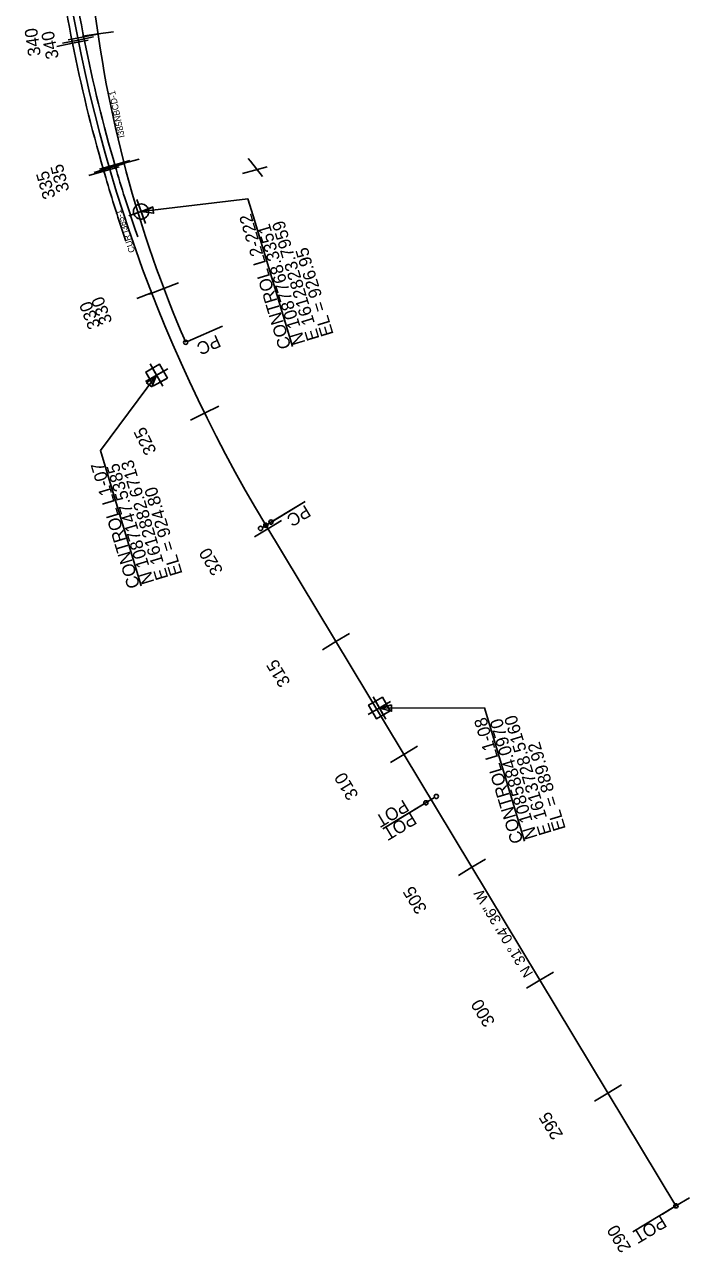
# Model space of a CAD drawing. Extents: x 1603447 to 1622636, y 1083818 to 1103958.
# Drawn here: x 1612382 to 1614905, y 1083818 to 1088478 of the extents above; entities that cross this region are included whole.
import ezdxf

# ---------------------------------------------------------------- set-up
doc = ezdxf.new("R2010")
doc.units = 0
for name, color, linetype in [('Level 1', 7, 'Continuous'), ('RD_HC_Points', 7, 'Continuous'), ('RD_HC_SUR_Bearing_TX400', 7, 'Continuous'), ('RD_HC_SUR_CL400', 7, 'Continuous'), ('RD_HC_SUR_PC_PT_400', 7, 'Continuous'), ('RD_HC_SUR_Tic400', 7, 'Continuous'), ('RD_HC_SUR_TX_Sta400', 7, 'Continuous'), ('RD_SHT_Misc1', 7, 'Continuous'), ('RD_TX_Misc1', 7, 'Continuous')]:
    doc.layers.add(name, color=color, linetype=linetype)

msp = doc.modelspace()

# ---------------------------------------------------------------- linework, layer by layer
at = {"layer": 'RD_HC_Points'}
for p, q in [((1613248.8, 1087751.3), (1613398, 1087255.6)), ((1612687.5, 1086802.4), (1612824.4, 1086347.2)), ((1614142.4, 1085834), (1614279.3, 1085379))]:
    msp.add_line(p, q, dxfattribs=at)
for points in [[(1613248.8, 1087751.3), (1613229.2, 1087816.4), (1612823.8, 1087768.3)], [(1612687.5, 1086802.4), (1612669.6, 1086861.9), (1612882.7, 1087147.5)], [(1614142.4, 1085834), (1614127.1, 1085884.6), (1613728.5, 1085884.1)]]:
    msp.add_lwpolyline(points, dxfattribs=at)
for points in [[(1612868.4, 1087786.1), (1612823.8, 1087768.3), (1612871.3, 1087761.5)], [(1612864.9, 1087102.9), (1612882.7, 1087147.5), (1612845, 1087117.8)], [(1613774.9, 1085896.6), (1613728.5, 1085884.1), (1613774.9, 1085871.7)]]:
    msp.add_lwpolyline(points, close=True, dxfattribs=at)
at = {"layer": 'RD_HC_SUR_CL400'}
for p, q in [((1612689.6, 1087897.9), (1612681.1, 1087927)), ((1612811.9, 1087671.8), (1612802, 1087700.5)), ((1614854, 1083994.9), (1613297.3, 1086577.7))]:
    msp.add_line(p, q, dxfattribs=at)
for centre, radius, start, end in [((1618204.6, 1089535.2), 5752.8, 186.3858, 196.23352), ((1618204.6, 1089535.2), 5729.6, 186.3858, 211.0768), ((1618204.6, 1089535.2), 5706.3, 186.3858, 196.2335), ((1617212.5, 1089104.4), 4600, 186.3858, 203.4744), ((1617613.8, 1089363.2), 5091, 196.2335, 199.0628), ((1617623, 1089334.3), 5138.3, 196.2335, 199.0628)]:
    msp.add_arc(centre, radius, start, end, dxfattribs=at)
at = {"layer": 'RD_HC_SUR_PC_PT_400'}
for p, q in [((1613000.5, 1087275.2), (1613132.3, 1087332.8)), ((1613284.3, 1086569.8), (1613407.4, 1086644)), ((1613304.2, 1086581.8), (1613427.3, 1086656)), ((1613324.1, 1086593.8), (1613447.2, 1086668)), ((1613937.9, 1085544.4), (1613780.8, 1085449.7)), ((1613898.1, 1085520.4), (1613741, 1085425.7)), ((1614847.1, 1083990.7), (1614690, 1083896.1))]:
    msp.add_line(p, q, dxfattribs=at)
for centre in [(1612993.2, 1087272), (1613317.2, 1086589.7), (1613277.4, 1086565.7), (1613297.3, 1086577.7), (1613904.9, 1085524.5), (1613944.7, 1085548.5), (1614854, 1083994.9)]:
    msp.add_circle(centre, 8, dxfattribs=at)
at = {"layer": 'RD_HC_SUR_Tic400'}
for p, q in [((1612584.8, 1088419.1), (1612525.9, 1088407.4)), ((1612606, 1088431.5), (1612547.1, 1088419.9)), ((1612563.5, 1088406.6), (1612622.4, 1088418.4)), ((1612584.8, 1088419.1), (1612643.6, 1088430.8)), ((1612660.4, 1088442.2), (1612601, 1088433.5)), ((1612606, 1088431.5), (1612664.9, 1088443.1)), ((1612660.4, 1088442.2), (1612719.8, 1088450.8)), ((1612563.5, 1088406.6), (1612504.7, 1088394.9)), ((1612605.1, 1088321.2), (1612605.1, 1088321.2)), ((1612626.2, 1088333.6), (1612626.2, 1088333.6)), ((1612675.8, 1088343.4), (1612675.8, 1088343.4)), ((1612584, 1088308.8), (1612584, 1088308.8)), ((1612648.1, 1088236), (1612648.1, 1088236)), ((1612693.3, 1088244.9), (1612693.3, 1088244.9)), ((1612606.2, 1088211.3), (1612606.2, 1088211.3)), ((1612627.1, 1088223.6), (1612627.1, 1088223.6)), ((1612671.7, 1088138.8), (1612671.7, 1088138.8)), ((1612713, 1088146.9), (1612713, 1088146.9)), ((1612630, 1088114.1), (1612630, 1088114.1)), ((1612650.9, 1088126.5), (1612650.9, 1088126.5)), ((1612697.1, 1088042.1), (1612697.1, 1088042.1)), ((1612655.6, 1088017.5), (1612655.6, 1088017.5)), ((1612676.3, 1088029.8), (1612676.3, 1088029.8)), ((1612759.1, 1087952.3), (1612701, 1087937.2)), ((1612703.4, 1087933.5), (1612761, 1087950.3)), ((1612724.1, 1087945.8), (1612781.7, 1087962.5)), ((1612759.1, 1087952.3), (1612817.2, 1087967.3)), ((1612682.8, 1087921.2), (1612625.2, 1087904.5)), ((1612703.4, 1087933.5), (1612645.8, 1087916.7)), ((1612724.1, 1087945.8), (1612666.4, 1087929.1)), ((1612682.8, 1087921.2), (1612740.4, 1087938)), ((1612711.3, 1087825.4), (1612711.3, 1087825.4)), ((1612732.2, 1087837.8), (1612732.2, 1087837.8)), ((1612752.8, 1087850), (1612752.8, 1087850)), ((1612741.6, 1087730.1), (1612741.6, 1087730.1)), ((1612762.7, 1087742.5), (1612762.7, 1087742.5)), ((1612783.5, 1087754.9), (1612783.5, 1087754.9)), ((1612794.8, 1087647.8), (1612794.8, 1087647.8)), ((1612828.6, 1087553.7), (1612828.6, 1087553.7)), ((1612910.4, 1087476), (1612966.5, 1087497.2)), ((1612864, 1087460.2), (1612808, 1087438.4)), ((1612910.4, 1087476), (1612854.3, 1087454.7)), ((1612901, 1087367.3), (1612901, 1087367.3)), ((1612946.1, 1087382.7), (1612946.1, 1087382.7)), ((1612939.6, 1087275), (1612939.6, 1087275)), ((1612984.5, 1087290.3), (1612984.5, 1087290.3)), ((1612979.9, 1087183.5), (1612979.9, 1087183.5)), ((1613021.7, 1087092.7), (1613021.7, 1087092.7)), ((1613065.1, 1087002.6), (1613119, 1087029.1)), ((1613065.1, 1087002.6), (1613011.3, 1086976.1)), ((1613110.1, 1086913.3), (1613110.1, 1086913.3)), ((1613156.7, 1086824.8), (1613156.7, 1086824.8)), ((1613204.7, 1086737.1), (1613204.7, 1086737.1)), ((1613254.3, 1086650.3), (1613254.3, 1086650.3)), ((1613305.4, 1086564.3), (1613254, 1086533.3)), ((1613305.4, 1086564.3), (1613356.8, 1086595.3)), ((1613357, 1086478.6), (1613357, 1086478.6)), ((1613408.6, 1086393), (1613408.6, 1086393)), ((1613460.3, 1086307.3), (1613460.3, 1086307.3)), ((1613511.9, 1086221.7), (1613511.9, 1086221.7)), ((1613563.5, 1086136), (1613512.1, 1086105.1)), ((1613563.5, 1086136), (1613614.9, 1086167)), ((1613615.1, 1086050.4), (1613615.1, 1086050.4)), ((1613666.7, 1085964.8), (1613666.7, 1085964.8)), ((1613718.4, 1085879.1), (1613718.4, 1085879.1)), ((1613770, 1085793.5), (1613770, 1085793.5)), ((1613821.6, 1085707.8), (1613873, 1085738.8)), ((1613821.6, 1085707.8), (1613770.2, 1085676.8)), ((1613873.2, 1085622.2), (1613873.2, 1085622.2)), ((1613924.8, 1085536.5), (1613924.8, 1085536.5)), ((1613976.4, 1085450.9), (1613976.4, 1085450.9)), ((1614028.1, 1085365.2), (1614028.1, 1085365.2)), ((1614079.7, 1085279.6), (1614131.1, 1085310.5)), ((1614079.7, 1085279.6), (1614028.3, 1085248.6)), ((1614131.3, 1085193.9), (1614131.3, 1085193.9)), ((1614182.9, 1085108.3), (1614182.9, 1085108.3)), ((1614234.5, 1085022.6), (1614234.5, 1085022.6)), ((1614286.2, 1084937), (1614286.2, 1084937)), ((1614337.8, 1084851.3), (1614389.2, 1084882.3)), ((1614337.8, 1084851.3), (1614286.4, 1084820.4)), ((1614389.4, 1084765.7), (1614389.4, 1084765.7)), ((1614441, 1084680), (1614441, 1084680)), ((1614492.6, 1084594.4), (1614492.6, 1084594.4)), ((1614544.3, 1084508.7), (1614544.3, 1084508.7)), ((1614595.9, 1084423.1), (1614647.3, 1084454.1)), ((1614595.9, 1084423.1), (1614544.5, 1084392.1)), ((1614647.5, 1084337.4), (1614647.5, 1084337.4)), ((1614699.1, 1084251.8), (1614699.1, 1084251.8)), ((1614750.7, 1084166.2), (1614750.7, 1084166.2)), ((1614802.3, 1084080.5), (1614802.3, 1084080.5)), ((1614854, 1083994.9), (1614802.6, 1083963.9)), ((1614854, 1083994.9), (1614905.4, 1084025.8))]:
    msp.add_line(p, q, dxfattribs=at)
at = {"layer": 'RD_HC_SUR_TX_Sta400'}
for p, q in [((1613230.9, 1087969.3), (1613238.6, 1087959.6)), ((1613238.6, 1087959.6), (1613285.2, 1087901)), ((1613209.1, 1087912.5), (1613303.1, 1087938))]:
    msp.add_line(p, q, dxfattribs=at)
at = {"layer": 'RD_SHT_Misc1'}
for p, q in [((1612840.1, 1087722.4), (1612807.5, 1087814.3)), ((1612777.9, 1087752), (1612869.7, 1087784.7)), ((1612823.8, 1087768.3), (1612796.7, 1087758.7)), ((1612814.2, 1087795.4), (1612823.8, 1087768.3)), ((1612823.8, 1087768.3), (1612850.9, 1087778)), ((1612833.4, 1087741.2), (1612823.8, 1087768.3)), ((1612840.3, 1087123.3), (1612925, 1087171.7)), ((1612906.9, 1087105.2), (1612858.5, 1087189.9)), ((1612882.7, 1087147.5), (1612867.8, 1087173.6)), ((1612908.7, 1087162.4), (1612882.7, 1087147.5)), ((1612856.6, 1087132.7), (1612882.7, 1087147.5)), ((1612882.7, 1087147.5), (1612897.6, 1087121.5)), ((1613686.2, 1085859.9), (1613770.8, 1085908.3)), ((1613752.7, 1085841.8), (1613704.3, 1085926.4)), ((1613728.5, 1085884.1), (1613713.6, 1085910.1)), ((1613754.6, 1085899), (1613728.5, 1085884.1)), ((1613702.5, 1085869.2), (1613728.5, 1085884.1)), ((1613728.5, 1085884.1), (1613743.4, 1085858.1))]:
    msp.add_line(p, q, dxfattribs=at)
for points in [[(1612923.6, 1087136.4), (1612893.8, 1087188.5), (1612841.7, 1087158.7), (1612871.5, 1087106.6)], [(1613769.4, 1085872.9), (1613739.7, 1085925), (1613687.6, 1085895.3), (1613717.4, 1085843.2)]]:
    msp.add_lwpolyline(points, close=True, dxfattribs=at)
for points in [[(1612867.8, 1087173.6), (1612841.7, 1087158.7), (1612856.6, 1087132.7)], [(1612923.6, 1087136.4), (1612908.7, 1087162.4)], [(1612897.6, 1087121.5), (1612923.6, 1087136.4)], [(1613713.6, 1085910.1), (1613687.6, 1085895.3), (1613702.5, 1085869.2)], [(1613769.4, 1085872.9), (1613754.6, 1085899)], [(1613743.4, 1085858.1), (1613769.4, 1085872.9)]]:
    msp.add_lwpolyline(points, dxfattribs=at)
msp.add_circle((1612823.8, 1087768.3), 28.8, dxfattribs=at)
for start, end in [(19.573, 109.573), (199.573, 289.573)]:
    msp.add_arc((1612823.8, 1087768.3), 28.8, start, end, dxfattribs=at)

# ---------------------------------------------------------------- texts
at = {"layer": 'Level 1'}
for s, rotation, p in [('335', 106.2335, (1612500.1, 1087823.5)), ('335', 104.4734, (1612552.1, 1087848.5)), ('325', 116.2335, (1612884, 1086859)), ('315', 121.0768, (1613392.7, 1085981.6)), ('305', 121.0768, (1613911.3, 1085121.2)), ('295', 121.0768, (1614427.5, 1084264.7))]:
    msp.add_text(s, height=48, rotation=rotation, dxfattribs=at).set_placement(p)
at = {"layer": 'RD_HC_Points'}
for s, p in [('CONTROL L2-222', (1613394.2, 1087254.4)), ('N 1087768.3351', (1613447.8, 1087270.6)), ('E 1612823.7959', (1613501.4, 1087286.7)), ('EL = 926.95', (1613555, 1087302.9)), ('CONTROL L1-07', (1612820.6, 1086346.1)), ('N 1087147.5385', (1612874.2, 1086362.2)), ('E 1612882.6713', (1612927.8, 1086378.4)), ('EL = 924.80', (1612981.5, 1086394.5)), ('E 1613728.5160', (1614382.7, 1085410.1)), ('CONTROL L1-08', (1614275.4, 1085377.9)), ('N 1085884.0970', (1614329.1, 1085394)), ('EL = 889.92', (1614436.3, 1085426.3))]:
    msp.add_text(s, height=48, rotation=106.7478, dxfattribs=at).set_placement(p)
at = {"layer": 'RD_HC_SUR_Bearing_TX400'}
msp.add_text('N 31%%d 04\' 36" W', height=40, rotation=121.0768, dxfattribs=at).set_placement((1614313.6, 1084877.1))
at = {"layer": 'RD_HC_SUR_PC_PT_400'}
for s, rotation, p in [('PC', 203.6031, (1613112.3, 1087301.6)), ('PC', 211.0768, (1613448.4, 1086656.9)), ('POT', 211.0768, (1613821.1, 1085538.2)), ('POT', 211.0768, (1613850.3, 1085489.2)), ('POT', 211.0768, (1614799.3, 1083959.6))]:
    msp.add_text(s, height=48, rotation=rotation, dxfattribs=at).set_placement(p)
at = {"layer": 'RD_HC_SUR_TX_Sta400'}
for s, rotation, p in [('340', 98.2456, (1612443.7, 1088361.2)), ('340', 101.2335, (1612512, 1088351.5)), ('330', 110.7012, (1612715.7, 1087350)), ('330', 111.2335, (1612671.1, 1087332.6)), ('320', 121.0768, (1613137.2, 1086405.6)), ('310', 121.0768, (1613651, 1085553.1)), ('300', 121.0768, (1614169.5, 1084692.7)), ('290', 121.0768, (1614685.7, 1083836.2))]:
    msp.add_text(s, height=48, rotation=rotation, dxfattribs=at).set_placement(p)
at = {"layer": 'RD_TX_Misc1'}
for s, rotation, p in [('I385NBCD-1', 101.9381, (1612762.2, 1088050.9)), ('CUR I385-1', 108.7833, (1612801.7, 1087616.7))]:
    msp.add_text(s, height=24, rotation=rotation, dxfattribs=at).set_placement(p)

doc.saveas('drawing.dxf')
